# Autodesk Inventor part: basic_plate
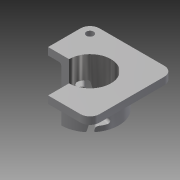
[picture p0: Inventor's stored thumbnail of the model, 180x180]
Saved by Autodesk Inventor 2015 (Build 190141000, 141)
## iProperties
Created: 2005-10
Part Number: basic_plate
Document SubType Name: Modeling
Designer: hassen
Density: 1 g/cm^3
Material: Generic
Appearance: Steel
Author: hassen
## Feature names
1. Extrusion1
2. Extrusion2
3. Hole1
4. Extrusion3
5. Sweep3
6. Fillet2
7. Fillet3
8. Fillet4
9. Circular Pattern1
10. Fillet5
11. Fillet6
12. Chamfer1
13. Hole2
## Parameters: d2 = 7 mm, d3 = 0, d5 = 55 mm, d6 = 24 mm, d7 = 0, d11 = 6 mm, d12 = 4 mm, d13 = 2 mm, d14 = 90 deg, d15 = 8 mm, d16 = 118 deg, d17 = 6 mm, d18 = 0, d19 = 45 deg, d20 = 5 mm, d21 = 75 deg, d26 = 30 deg, d27 = 0, d28 = 2.5 mm, d29 = 1 mm, d31 = 180 deg, d33 = 9 mm, d34 = 2 mm, d35 = 0.5 mm, d36 = 2 mm, d37 = 45 deg, d40 = 7 mm, d41 = 6 mm, d42 = 12 mm, d43 = 2 mm, d44 = 90 deg, d45 = 8 mm, d46 = 118 deg, d47 = 0
